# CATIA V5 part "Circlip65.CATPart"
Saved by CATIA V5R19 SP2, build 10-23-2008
Part number: Circlip65
Definition: NONE
Nomenclature: 1
Source: Unknown
Description: PART-1-DESC
Bounding box of the stored display mesh (mm): x -32.5 to 32.5, y -32.421 to 32.322, z 0 to 2
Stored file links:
  D:\SCHOOL\FRANCE\BANC_POUTRE_EN_MOUSSE\Circlip65.CATPart
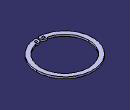
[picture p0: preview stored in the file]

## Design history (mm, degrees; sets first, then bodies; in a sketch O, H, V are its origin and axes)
Body1 "1" (main body)
  Solid1: solid without history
